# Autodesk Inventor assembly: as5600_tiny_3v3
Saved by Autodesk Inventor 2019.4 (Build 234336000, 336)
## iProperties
Created: 2020-10
Part Number: as5600_tiny_3v3
Document SubType Name: Assembly
Designer: Administrator
Title: as5600_tiny_3v3 v1
Author: Administrator
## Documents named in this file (3)
- c:\worker\convert-fusion-r08\tmp\job-1\28\output\files\0f32c761-68ca-407a-9a1e-94d9330a9fa0\645c9e1f-3a86-4307-9b7f-c0e3e99fb7ae.zip.iam
- c:\worker\convert-fusion-r08\tmp\job-1\28\output\files\0f32c761-68ca-407a-9a1e-94d9330a9fa0\Board.ipt
- c:\worker\convert-fusion-r08\tmp\job-1\28\output\files\0f32c761-68ca-407a-9a1e-94d9330a9fa0\Packages.iam
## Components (2 placed, 2 different names)
1. Board:1
2. Packages:1 [sub-assembly]
